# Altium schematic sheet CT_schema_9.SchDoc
size 308 x 210 mm
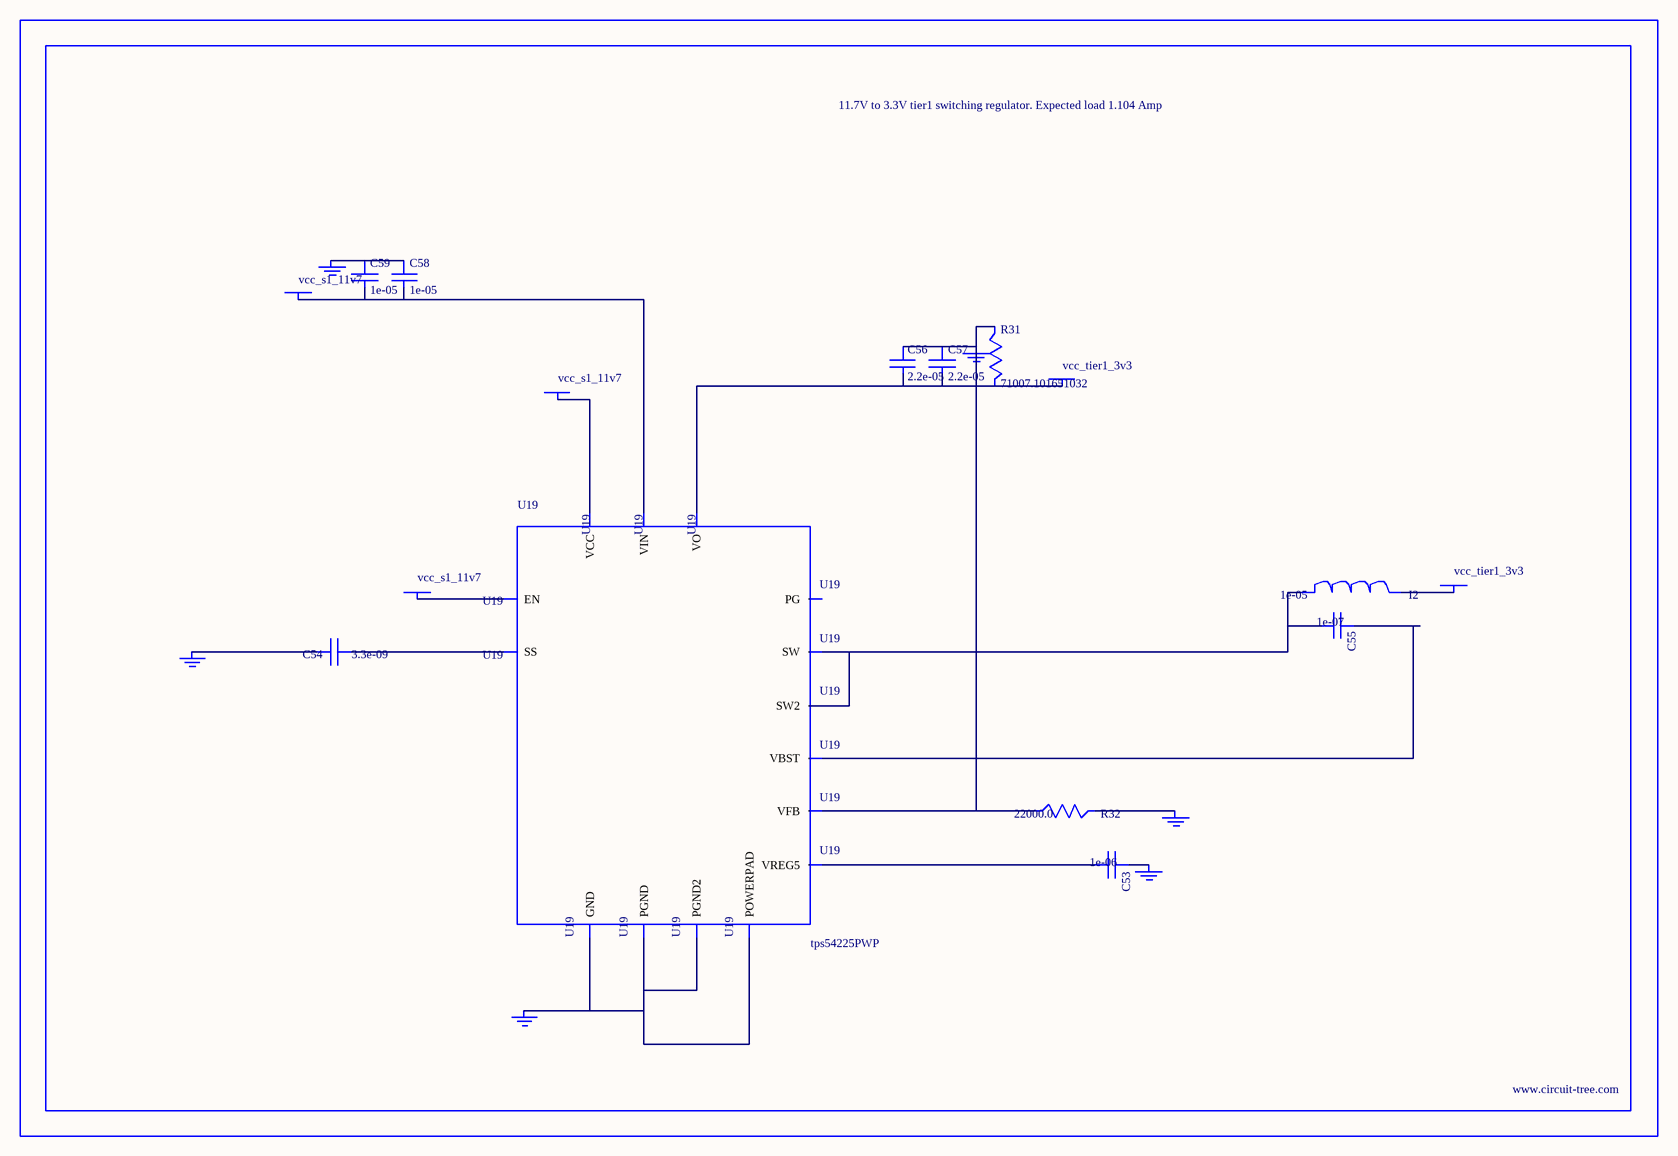
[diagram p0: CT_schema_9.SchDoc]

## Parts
BORDER8  (no value)
C53  1e-06  [C0603]
C54  3.3e-09  [C0402]
C55  1e-07  [C0402]
C56  2.2e-05  [C1210]
C57  2.2e-05  [C1210]
C58  1e-05  [C1206]
C59  1e-05  [C1206]
GND_INSTANCE_8_0  (no value)
GND_INSTANCE_8_1  (no value)
GND_INSTANCE_8_2  (no value)
GND_INSTANCE_8_3  (no value)
GND_INSTANCE_8_4  (no value)
GND_INSTANCE_8_5  (no value)
I2  1e-05  [IND_PM3316]
POWER_INSTANCE_8_0  vcc_tier1_3v3
POWER_INSTANCE_8_1  vcc_s1_11v7
POWER_INSTANCE_8_2  vcc_tier1_3v3
POWER_INSTANCE_8_3  vcc_s1_11v7
POWER_INSTANCE_8_4  vcc_s1_11v7
R31  71007.101651032  [R0603]
R32  22000.0  [R0603]
U19  tps54225PWP  [HTSSOP14]

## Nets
NetC53_1: C53.1 GND_INSTANCE_8_2.0(GND)
NetC53_2: C53.2 U19.3(VREG5)
NetC54_1: C54.1 U19.4(SS)
NetC54_2: C54.2 GND_INSTANCE_8_3.0(GND)
NetC55_1: C55.1 U19.12(VBST)
NetC55_2: C55.2 I2.1 U19.10(SW) U19.11(SW2)
NetC56_1: C56.1 C57.1 GND_INSTANCE_8_0.0(GND) R31.1 R32.1 U19.2(VFB)
NetC56_2: C56.2 C57.2 POWER_INSTANCE_8_0.0(PWR) R31.2 U19.1(VO)
NetC58_1: C58.1 C59.1 GND_INSTANCE_8_5.0(GND)
NetC58_2: C58.2 C59.2 POWER_INSTANCE_8_3.0(PWR) U19.13(VIN)
NetGND_INSTANCE_8_1_0: GND_INSTANCE_8_1.0(GND) R32.2
NetGND_INSTANCE_8_4_0: GND_INSTANCE_8_4.0(GND) U19.5(GND) U19.8(PGND) U19.9(PGND2) U19.15(POWERPAD)
NetI2_2: I2.2 POWER_INSTANCE_8_2.0(PWR)
NetPOWER_INSTANCE_8_1_0: POWER_INSTANCE_8_1.0(PWR) U19.7(EN)
NetPOWER_INSTANCE_8_4_0: POWER_INSTANCE_8_4.0(PWR) U19.14(VCC)

Not connected (* = marked no-connect by the designer): U19 6(PG)

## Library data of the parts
BORDER8 = BORDER_PAGE8
C53 = C0603C105K3RACTU
C54 = C0402C332K3RAC
C55 = C0402C104K3RACTU
C56 C57 = GRM32ER61E226ME15L
C58 C59 = C1206C106K3RACTU
GND_INSTANCE_8_0-GND_INSTANCE_8_5 = GND
I2 = PM3316-100M-RC
POWER_INSTANCE_8_0-POWER_INSTANCE_8_4 = PWR
R31 = R31
R32 = RC0603JR-0722KL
